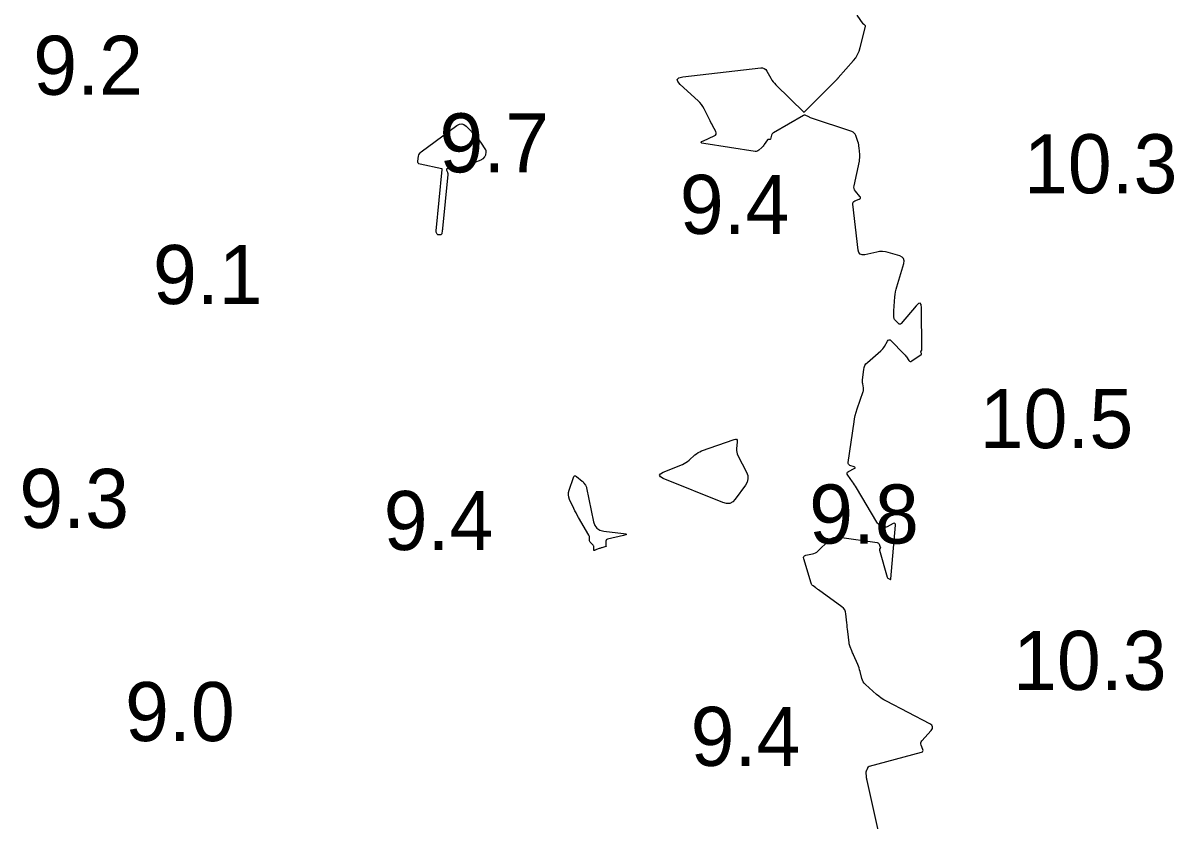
# Model space of a CAD drawing. Extents: x 1023796 to 1112670, y 656573 to 837340.
# Drawn here: x 1100521.5 to 1100619, y 688031.7 to 688099.2 of the extents above; entities that cross this region are included whole.
import ezdxf

# ---------------------------------------------------------------- set-up
doc = ezdxf.new("R2010")
doc.units = 0
doc.layers.add('V-CHAN-CONT-10FT', color=7, linetype='Continuous')
doc.layers.add('V-TOPO-SOUN', color=7, linetype='Continuous')

msp = doc.modelspace()

# ---------------------------------------------------------------- linework, layer by layer
at = {"layer": 'V-CHAN-CONT-10FT'}
msp.add_lwpolyline([(1100594.153, 688030.034), (1100593.005, 688035.106), (1100592.99, 688035.181), (1100592.977, 688035.255), (1100592.968, 688035.33), (1100592.961, 688035.406), (1100592.936, 688035.787), (1100592.935, 688035.823), (1100592.939, 688035.858), (1100592.947, 688035.892), (1100592.959, 688035.926), (1100593.022, 688036.077), (1100593.032, 688036.1), (1100593.044, 688036.124), (1100593.056, 688036.146), (1100593.07, 688036.169), (1100593.125, 688036.257), (1100593.141, 688036.277), (1100593.159, 688036.293), (1100593.18, 688036.306), (1100593.203, 688036.314), (1100597.61, 688037.49), (1100597.691, 688037.525), (1100597.739, 688037.576), (1100597.753, 688037.645), (1100597.734, 688037.731), (1100597.59, 688038.109), (1100597.567, 688038.201), (1100597.57, 688038.288), (1100597.598, 688038.371), (1100597.652, 688038.45), (1100598.428, 688039.338), (1100598.535, 688039.503), (1100598.553, 688039.651), (1100598.482, 688039.782), (1100598.322, 688039.897), (1100594.65, 688041.808), (1100594.423, 688041.936), (1100594.205, 688042.077), (1100593.996, 688042.232), (1100593.797, 688042.4), (1100592.857, 688043.244), (1100592.753, 688043.352), (1100592.668, 688043.472), (1100592.602, 688043.603), (1100592.556, 688043.746), (1100592.407, 688044.339), (1100592.367, 688044.486), (1100592.321, 688044.632), (1100592.269, 688044.775), (1100592.211, 688044.916), (1100591.853, 688045.745), (1100591.817, 688045.83), (1100591.781, 688045.914), (1100591.745, 688045.999), (1100591.709, 688046.084), (1100591.568, 688046.423), (1100591.536, 688046.508), (1100591.51, 688046.596), (1100591.49, 688046.685), (1100591.476, 688046.775), (1100591.367, 688047.722), (1100591.346, 688047.909), (1100591.325, 688048.095), (1100591.305, 688048.281), (1100591.286, 688048.467), (1100591.211, 688049.213), (1100591.176, 688049.389), (1100591.107, 688049.547), (1100591.005, 688049.685), (1100590.87, 688049.805), (1100588.874, 688051.245), (1100588.817, 688051.286), (1100588.761, 688051.328), (1100588.704, 688051.371), (1100588.648, 688051.413), (1100588.424, 688051.584), (1100588.372, 688051.63), (1100588.33, 688051.682), (1100588.296, 688051.74), (1100588.27, 688051.805), (1100587.635, 688053.865), (1100587.616, 688053.984), (1100587.642, 688054.077), (1100587.711, 688054.142), (1100587.826, 688054.181), (1100588.371, 688054.284), (1100588.503, 688054.319), (1100588.626, 688054.371), (1100588.739, 688054.441), (1100588.844, 688054.529), (1100589.775, 688055.432), (1100589.972, 688055.588), (1100590.188, 688055.687), (1100590.421, 688055.732), (1100590.671, 688055.721), (1100593.864, 688055.248), (1100593.916, 688055.234), (1100593.958, 688055.209), (1100593.992, 688055.173), (1100594.017, 688055.126), (1100594.122, 688054.853), (1100594.128, 688054.831), (1100594.129, 688054.809), (1100594.124, 688054.789), (1100594.113, 688054.769), (1100594.06, 688054.69), (1100594.049, 688054.669), (1100594.044, 688054.648), (1100594.043, 688054.627), (1100594.047, 688054.604), (1100594.716, 688052.313), (1100594.729, 688052.279), (1100594.749, 688052.251), (1100594.774, 688052.227), (1100594.805, 688052.208), (1100594.941, 688052.142), (1100594.971, 688052.132), (1100594.993, 688052.136), (1100595.008, 688052.153), (1100595.015, 688052.184), (1100595.408, 688056.722), (1100595.404, 688056.823), (1100595.369, 688056.88), (1100595.304, 688056.891), (1100595.208, 688056.857), (1100594.698, 688056.597), (1100594.62, 688056.567), (1100594.542, 688056.557), (1100594.463, 688056.566), (1100594.385, 688056.595), (1100594.071, 688056.749), (1100593.997, 688056.792), (1100593.931, 688056.844), (1100593.874, 688056.905), (1100593.825, 688056.976), (1100592.099, 688059.884), (1100592.018, 688060.016), (1100591.935, 688060.147), (1100591.849, 688060.277), (1100591.76, 688060.404), (1100591.359, 688060.965), (1100591.311, 688061.058), (1100591.308, 688061.14), (1100591.349, 688061.211), (1100591.435, 688061.271), (1100591.918, 688061.511), (1100591.981, 688061.552), (1100592.001, 688061.591), (1100591.977, 688061.627), (1100591.909, 688061.66), (1100591.55, 688061.787), (1100591.474, 688061.827), (1100591.423, 688061.882), (1100591.398, 688061.953), (1100591.398, 688062.039), (1100591.896, 688065.462), (1100591.943, 688065.743), (1100592.004, 688066.022), (1100592.077, 688066.297), (1100592.163, 688066.569), (1100592.665, 688068.033), (1100592.688, 688068.113), (1100592.7, 688068.194), (1100592.701, 688068.275), (1100592.693, 688068.358), (1100592.638, 688068.69), (1100592.627, 688068.773), (1100592.622, 688068.856), (1100592.622, 688068.939), (1100592.629, 688069.023), (1100592.724, 688069.917), (1100592.757, 688070.086), (1100592.819, 688070.241), (1100592.911, 688070.38), (1100593.031, 688070.504), (1100594.16, 688071.48), (1100594.252, 688071.566), (1100594.335, 688071.659), (1100594.411, 688071.759), (1100594.478, 688071.865), (1100594.731, 688072.304), (1100594.798, 688072.388), (1100594.871, 688072.423), (1100594.95, 688072.408), (1100595.035, 688072.342), (1100596.113, 688071.242), (1100596.174, 688071.178), (1100596.231, 688071.111), (1100596.286, 688071.042), (1100596.337, 688070.97), (1100596.538, 688070.679), (1100596.592, 688070.622), (1100596.65, 688070.595), (1100596.715, 688070.599), (1100596.785, 688070.634), (1100597.588, 688071.182), (1100597.606, 688071.199), (1100597.617, 688071.219), (1100597.62, 688071.241), (1100597.614, 688071.265), (1100597.572, 688071.379), (1100597.567, 688071.4), (1100597.567, 688071.42), (1100597.572, 688071.439), (1100597.582, 688071.458), (1100597.631, 688071.533), (1100597.642, 688071.552), (1100597.65, 688071.572), (1100597.655, 688071.593), (1100597.656, 688071.615), (1100597.626, 688075.131), (1100597.595, 688075.408), (1100597.506, 688075.529), (1100597.361, 688075.493), (1100597.159, 688075.301), (1100595.889, 688073.809), (1100595.831, 688073.758), (1100595.773, 688073.74), (1100595.713, 688073.754), (1100595.652, 688073.801), (1100595.378, 688074.08), (1100595.336, 688074.131), (1100595.306, 688074.187), (1100595.287, 688074.248), (1100595.28, 688074.314), (1100595.275, 688074.588), (1100595.275, 688074.657), (1100595.276, 688074.725), (1100595.278, 688074.794), (1100595.282, 688074.862), (1100595.363, 688076.048), (1100595.384, 688076.267), (1100595.417, 688076.484), (1100595.462, 688076.699), (1100595.519, 688076.912), (1100596.11, 688078.894), (1100596.143, 688079.116), (1100596.097, 688079.295), (1100595.973, 688079.431), (1100595.769, 688079.524), (1100594.798, 688079.813), (1100594.555, 688079.869), (1100594.31, 688079.894), (1100594.065, 688079.887), (1100593.818, 688079.848), (1100592.818, 688079.628), (1100592.596, 688079.611), (1100592.429, 688079.672), (1100592.317, 688079.81), (1100592.259, 688080.024), (1100591.796, 688083.906), (1100591.797, 688083.999), (1100591.825, 688084.077), (1100591.881, 688084.139), (1100591.962, 688084.184), (1100592.344, 688084.334), (1100592.419, 688084.376), (1100592.454, 688084.429), (1100592.448, 688084.491), (1100592.401, 688084.564), (1100592.018, 688085.013), (1100591.946, 688085.117), (1100591.903, 688085.228), (1100591.888, 688085.347), (1100591.902, 688085.473), (1100592.349, 688087.556), (1100592.373, 688087.693), (1100592.387, 688087.831), (1100592.391, 688087.97), (1100592.384, 688088.11), (1100592.334, 688088.679), (1100592.318, 688088.813), (1100592.294, 688088.945), (1100592.263, 688089.075), (1100592.224, 688089.204), (1100592.051, 688089.716), (1100591.997, 688089.833), (1100591.922, 688089.929), (1100591.826, 688090.004), (1100591.708, 688090.058), (1100588.217, 688091.229), (1100588.164, 688091.248), (1100588.112, 688091.27), (1100588.061, 688091.293), (1100588.011, 688091.319), (1100587.812, 688091.428), (1100587.762, 688091.449), (1100587.713, 688091.455), (1100587.664, 688091.448), (1100587.615, 688091.426), (1100585.063, 688089.957), (1100585.01, 688089.92), (1100584.967, 688089.874), (1100584.934, 688089.821), (1100584.911, 688089.761), (1100584.817, 688089.426), (1100584.807, 688089.403), (1100584.792, 688089.387), (1100584.772, 688089.378), (1100584.747, 688089.377), (1100584.637, 688089.386), (1100584.611, 688089.385), (1100584.588, 688089.378), (1100584.568, 688089.364), (1100584.551, 688089.345), (1100584.291, 688088.966), (1100584.241, 688088.897), (1100584.188, 688088.831), (1100584.131, 688088.768), (1100584.071, 688088.708), (1100583.823, 688088.473), (1100583.758, 688088.423), (1100583.688, 688088.391), (1100583.612, 688088.377), (1100583.531, 688088.381), (1100579.162, 688089.043), (1100579, 688089.082), (1100578.941, 688089.135), (1100578.984, 688089.201), (1100579.13, 688089.281), (1100580.05, 688089.685), (1100580.157, 688089.752), (1100580.215, 688089.837), (1100580.222, 688089.938), (1100580.179, 688090.058), (1100579.908, 688090.569), (1100579.841, 688090.697), (1100579.774, 688090.826), (1100579.709, 688090.955), (1100579.644, 688091.084), (1100579.196, 688091.984), (1100579.092, 688092.172), (1100578.972, 688092.347), (1100578.836, 688092.51), (1100578.684, 688092.661), (1100577.172, 688094.033), (1100576.956, 688094.282), (1100576.919, 688094.473), (1100577.06, 688094.606), (1100577.381, 688094.682), (1100583.988, 688095.443), (1100584.15, 688095.441), (1100584.291, 688095.396), (1100584.41, 688095.309), (1100584.507, 688095.178), (1100584.85, 688094.568), (1100584.94, 688094.42), (1100585.041, 688094.279), (1100585.151, 688094.145), (1100585.272, 688094.02), (1100587.675, 688091.674), (1100587.677, 688091.673), (1100587.678, 688091.672), (1100587.679, 688091.673), (1100587.679, 688091.676), (1100587.679, 688091.687), (1100587.679, 688091.689), (1100587.68, 688091.692), (1100587.681, 688091.694), (1100587.683, 688091.696), (1100590.344, 688094.367), (1100590.363, 688094.386), (1100590.381, 688094.405), (1100590.4, 688094.424), (1100590.418, 688094.443), (1100590.49, 688094.52), (1100590.508, 688094.54), (1100590.526, 688094.559), (1100590.543, 688094.579), (1100590.561, 688094.599), (1100591.85, 688096.066), (1100592.043, 688096.314), (1100592.202, 688096.579), (1100592.328, 688096.861), (1100592.42, 688097.161), (1100592.86, 688098.963), (1100592.863, 688098.988), (1100592.859, 688099.01), (1100592.849, 688099.03), (1100592.832, 688099.048), (1100592.751, 688099.115), (1100592.731, 688099.133), (1100592.712, 688099.151), (1100592.695, 688099.171), (1100592.679, 688099.192), (1100592.157, 688099.917)], dxfattribs=at)
for points in [[(1100560.703, 688088.424), (1100560.709, 688088.372), (1100560.704, 688088.319), (1100560.665, 688088.095), (1100560.653, 688088.045), (1100560.633, 688087.998), (1100560.607, 688087.954), (1100560.574, 688087.914), (1100560.429, 688087.761), (1100560.391, 688087.725), (1100560.35, 688087.693), (1100560.305, 688087.667), (1100560.258, 688087.645), (1100559.091, 688087.186), (1100558.923, 688087.126), (1100558.753, 688087.078), (1100558.579, 688087.04), (1100558.402, 688087.014), (1100557.433, 688086.902), (1100557.392, 688086.891), (1100557.369, 688086.871), (1100557.361, 688086.84), (1100557.371, 688086.799), (1100557.442, 688086.617), (1100557.457, 688086.571), (1100557.467, 688086.524), (1100557.47, 688086.477), (1100557.468, 688086.429), (1100557.02, 688081.849), (1100557.015, 688081.798), (1100557.01, 688081.747), (1100557.005, 688081.696), (1100557, 688081.644), (1100556.979, 688081.426), (1100556.97, 688081.386), (1100556.951, 688081.356), (1100556.922, 688081.336), (1100556.882, 688081.325), (1100556.692, 688081.299), (1100556.657, 688081.298), (1100556.626, 688081.308), (1100556.601, 688081.327), (1100556.58, 688081.356), (1100556.481, 688081.546), (1100556.477, 688081.553), (1100556.476, 688081.561), (1100556.476, 688081.569), (1100556.478, 688081.577), (1100556.489, 688081.609), (1100556.491, 688081.617), (1100556.493, 688081.625), (1100556.495, 688081.633), (1100556.496, 688081.641), (1100557.006, 688086.854), (1100557.006, 688086.859), (1100557.006, 688086.864), (1100557.005, 688086.869), (1100557.003, 688086.874), (1100556.994, 688086.894), (1100556.991, 688086.898), (1100556.988, 688086.902), (1100556.984, 688086.904), (1100556.979, 688086.906), (1100555.119, 688087.299), (1100555.029, 688087.332), (1100554.969, 688087.386), (1100554.939, 688087.461), (1100554.939, 688087.557), (1100555.001, 688087.984), (1100555.026, 688088.086), (1100555.068, 688088.177), (1100555.128, 688088.257), (1100555.206, 688088.326), (1100558.249, 688090.564), (1100558.453, 688090.674), (1100558.649, 688090.7), (1100558.839, 688090.642), (1100559.021, 688090.5), (1100559.896, 688089.6), (1100559.993, 688089.495), (1100560.085, 688089.385), (1100560.172, 688089.271), (1100560.253, 688089.152), (1100560.663, 688088.521), (1100560.688, 688088.473)], [(1100581.363, 688058.574), (1100581.082, 688058.55), (1100580.772, 688058.631), (1100575.734, 688060.686), (1100575.493, 688060.817), (1100575.412, 688060.948), (1100575.493, 688061.08), (1100575.734, 688061.211), (1100577.352, 688061.871), (1100577.504, 688061.941), (1100577.649, 688062.023), (1100577.785, 688062.117), (1100577.915, 688062.224), (1100578.416, 688062.674), (1100578.546, 688062.779), (1100578.684, 688062.871), (1100578.83, 688062.948), (1100578.984, 688063.012), (1100581.734, 688063.993), (1100581.856, 688064.018), (1100581.939, 688063.994), (1100581.984, 688063.92), (1100581.99, 688063.796), (1100581.939, 688063.201), (1100581.937, 688063.054), (1100581.954, 688062.912), (1100581.992, 688062.773), (1100582.05, 688062.638), (1100582.784, 688061.201), (1100582.887, 688060.921), (1100582.908, 688060.647), (1100582.845, 688060.38), (1100582.699, 688060.119), (1100581.835, 688058.933), (1100581.614, 688058.701)], [(1100570.906, 688055.49), (1100570.881, 688055.442), (1100570.873, 688055.381), (1100570.873, 688054.986), (1100570.873, 688054.979), (1100570.874, 688054.972), (1100570.876, 688054.966), (1100570.877, 688054.96), (1100570.886, 688054.934), (1100570.887, 688054.928), (1100570.886, 688054.924), (1100570.883, 688054.92), (1100570.878, 688054.918), (1100570.532, 688054.818), (1100570.473, 688054.8), (1100570.413, 688054.781), (1100570.355, 688054.761), (1100570.297, 688054.739), (1100569.93, 688054.597), (1100569.921, 688054.594), (1100569.912, 688054.592), (1100569.903, 688054.591), (1100569.894, 688054.59), (1100569.857, 688054.589), (1100569.849, 688054.59), (1100569.843, 688054.593), (1100569.84, 688054.599), (1100569.84, 688054.607), (1100569.859, 688054.863), (1100569.858, 688054.907), (1100569.848, 688054.948), (1100569.829, 688054.985), (1100569.801, 688055.02), (1100569.566, 688055.257), (1100569.531, 688055.298), (1100569.507, 688055.343), (1100569.492, 688055.392), (1100569.487, 688055.446), (1100569.487, 688055.667), (1100569.484, 688055.721), (1100569.474, 688055.774), (1100569.456, 688055.824), (1100569.432, 688055.873), (1100568.549, 688057.388), (1100568.444, 688057.572), (1100568.344, 688057.758), (1100568.247, 688057.947), (1100568.154, 688058.137), (1100567.789, 688058.903), (1100567.718, 688059.096), (1100567.687, 688059.291), (1100567.695, 688059.488), (1100567.744, 688059.688), (1100568.112, 688060.767), (1100568.158, 688060.858), (1100568.218, 688060.901), (1100568.291, 688060.896), (1100568.379, 688060.844), (1100568.856, 688060.462), (1100568.899, 688060.425), (1100568.94, 688060.384), (1100568.978, 688060.341), (1100569.013, 688060.295), (1100569.147, 688060.106), (1100569.178, 688060.058), (1100569.203, 688060.007), (1100569.223, 688059.954), (1100569.237, 688059.898), (1100569.821, 688057.017), (1100569.929, 688056.699), (1100570.111, 688056.459), (1100570.365, 688056.298), (1100570.691, 688056.216), (1100572.36, 688056.02), (1100572.551, 688055.987), (1100572.616, 688055.947), (1100572.555, 688055.901), (1100572.369, 688055.849), (1100571.006, 688055.546), (1100570.948, 688055.525)]]:
    msp.add_lwpolyline(points, close=True, dxfattribs=at)

# ---------------------------------------------------------------- texts
at = {"layer": 'V-TOPO-SOUN'}
for s, p in [('9.2', (1100522.342, 688093.17)), ('9.7', (1100556.762, 688086.6)), ('10.3 ', (1100606.292, 688084.83)), ('9.4', (1100577.132, 688081.39)), ('9.1', (1100532.487, 688075.45)), ('10.5 ', (1100602.545, 688063.25)), ('9.3', (1100521.162, 688056.49)), ('9.4', (1100552.042, 688054.62)), ('9.8', (1100588.092, 688055.17)), ('10.3 ', (1100605.372, 688042.77)), ('9.0', (1100530.123, 688038.44)), ('9.4', (1100578.052, 688036.34))]:
    msp.add_text(s, height=5, dxfattribs=at).set_placement(p)

doc.saveas('drawing.dxf')
